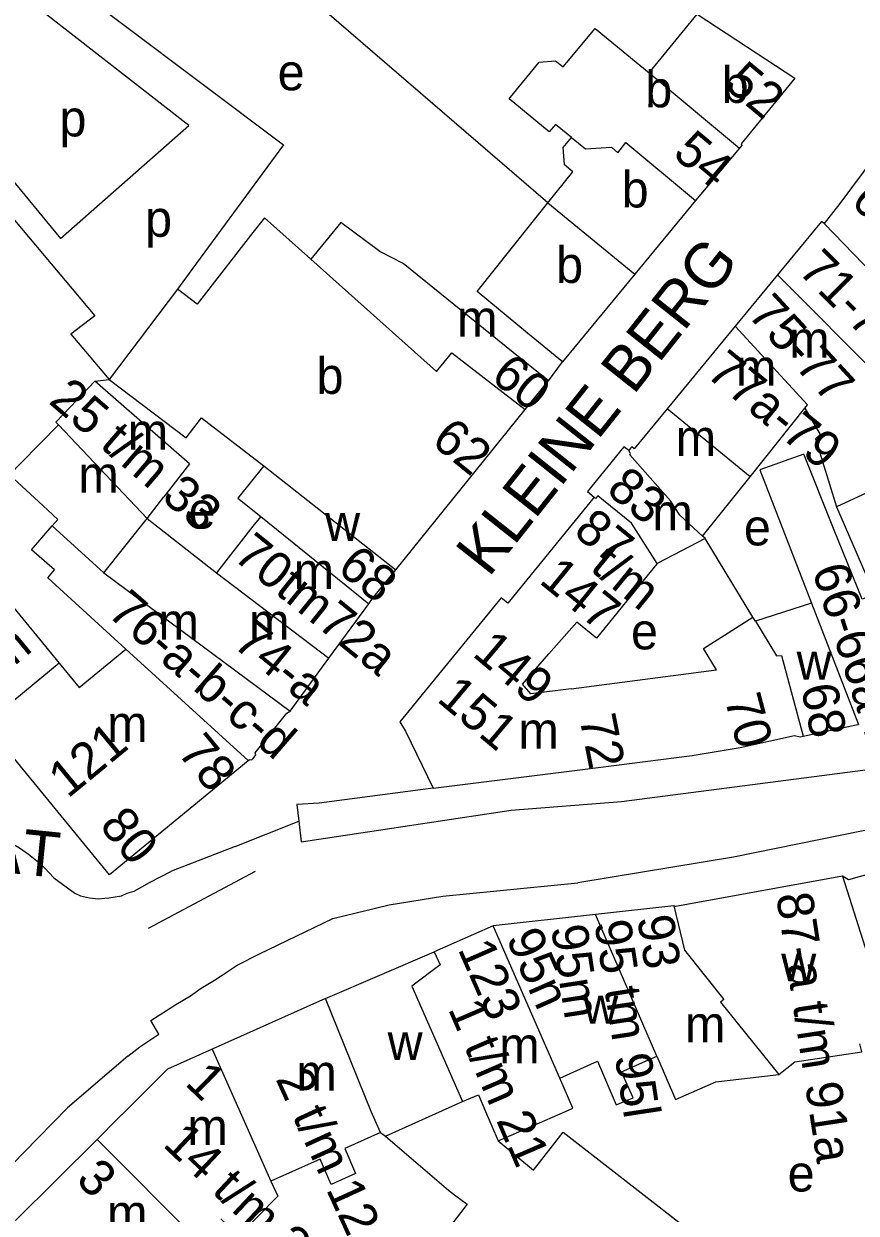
# Model space of a CAD drawing. Extents: x 160673 to 161924, y 382258 to 384145.
# Drawn here: x 160974.8 to 161066.4, y 382888.8 to 383019.8 of the extents above; entities that cross this region are included whole.
import ezdxf

# ---------------------------------------------------------------- set-up
doc = ezdxf.new("R2010")
doc.units = 0
for name, color, linetype in [('BLT_Basislijn', 7, 'Continuous'), ('BLT_Bebouwing', 7, 'Continuous'), ('BLT_Centroide', 7, 'Continuous'), ('BLT_Huisnummer', 7, 'Continuous'), ('BLT_Huisnummer_ tussenligend', 7, 'Continuous'), ('BLT_Huisnummer_reeks', 7, 'Continuous'), ('BLT_Onderdoorgang_en_onderverdeling', 7, 'Continuous'), ('BLT_Onderverdeling_panden', 7, 'Continuous'), ('BLT_Straatnaam', 7, 'Continuous')]:
    doc.layers.add(name, color=color, linetype=linetype)

msp = doc.modelspace()

# ---------------------------------------------------------------- linework, layer by layer
at = {"layer": 'BLT_Basislijn'}
for p, q in [((161032.47, 383000.08), (161006.81, 383022.18)), ((160993.29, 382992.74), (160991.68, 382990.55)), ((161032.54, 382980.45), (161034.1, 382982.55)), ((160982.58, 382980.41), (160984.16, 382980.62)), ((161055.06, 382954.43), (161049.79, 382963.11)), ((161004.83, 382933.8), (161005.04, 382931.98)), ((160998.06, 382929.16), (161005.04, 382931.98)), ((161005.04, 382931.98), (161005.31, 382929.69)), ((161070.35, 382931.54), (161052.91, 382928.01)), ((160998.06, 382929.16), (160991.03, 382926.45)), ((161052.91, 382928.01), (161035.79, 382925.18)), ((161000.23, 382926.42), (160988.47, 382920.16)), ((160978.08, 382925.73), (160980.4, 382924.03)), ((160986.23, 382906.1), (160987.54, 382907.11))]:
    msp.add_line(p, q, dxfattribs=at)
for points in [[(160973.74, 383029.17), (160976.69, 383026.54), (161003.35, 383006.47), (160993.29, 382992.74)], [(160951.81, 383024.3), (160982.58, 382987.62), (160979.94, 382985.6), (160984.16, 382980.62)], [(160963.06, 383015.22), (160978.82, 382996.13), (160992.96, 383008.58), (160973.33, 383023.89)], [(161005.31, 382929.69), (161028.45, 382933.19), (161040.57, 382934.15), (161068.29, 382937.74), (161084.05, 382942.53), (161102.21, 382948.46), (161126.1, 382957.64), (161137.52, 382962.54)], [(161019.84, 382935.61), (161007.3, 382933.96), (161004.83, 382933.8)], [(160969.96, 382931.06), (160971.09, 382930.66), (160972.19, 382930.19), (160973.25, 382929.64), (160974.28, 382929.02), (160975.27, 382928.34), (160976.2, 382927.59), (160977.09, 382926.78), (160978.08, 382925.73)], [(160980.4, 382924.03), (160981.03, 382923.75), (160981.33, 382923.66), (160982, 382923.53), (160983.01, 382923.43), (160983.69, 382923.47), (160984.15, 382923.52), (160985.52, 382923.76), (160986.15, 382924.02), (160986.93, 382924.26), (160988.62, 382925.21), (160991.03, 382926.45)], [(161008.81, 382921.24), (161015.02, 382922.76), (161020.91, 382923.7), (161035.79, 382925.18)], [(160987.54, 382907.11), (160989.65, 382908.51), (160988.76, 382910), (160991.51, 382911.77), (160993.13, 382912.73), (160994.29, 382913.59), (160995.76, 382914.45), (160996.62, 382915), (160998.28, 382916.11), (161000.73, 382917.36), (161008.81, 382921.24)], [(160986.23, 382906.1), (160979.59, 382900.39), (160974.77, 382895.48), (160965.77, 382886.24), (160962.43, 382882.73), (160958.51, 382877.83), (160957.53, 382876.57)], [(161027.01, 382896.76), (161030.91, 382893.53), (161034.17, 382897.73), (161056.14, 382880.6)], [(161014.61, 382897.26), (161021.53, 382891.31), (161022.19, 382890.81), (161023.58, 382889.8), (161012.25, 382875.03), (161002.61, 382861.65), (160999.48, 382858.26), (160999.64, 382857.69), (161009, 382847.54)]]:
    msp.add_lwpolyline(points, dxfattribs=at)
at = {"layer": 'BLT_Bebouwing'}
for p, q in [((161048.73, 383000.34), (161042.04, 382992.21)), ((161042.04, 382992.21), (161034.1, 382982.55)), ((161057.77, 382992.13), (161053.12, 382986.49)), ((160991.68, 382990.55), (160984.16, 382980.62)), ((161053.12, 382986.49), (161045.6, 382977.39)), ((160982.58, 382980.41), (160979.91, 382977.61)), ((160993.03, 382971.31), (160982.58, 382980.41)), ((161029.99, 382977.3), (161032.54, 382980.45)), ((161015.74, 382959.66), (161029.99, 382977.3)), ((161041.58, 382973.03), (161041.38, 382972.78)), ((160993.03, 382971.31), (160990.2, 382967.7)), ((161049.52, 382963.36), (161054.75, 382969.9)), ((161037.57, 382967.65), (161028.06, 382955.98)), ((161064.27, 382966.59), (161068.45, 382956.92)), ((160988.34, 382965.31), (160995.99, 382959.32)), ((161049.79, 382963.11), (161044.52, 382960.34)), ((161049.79, 382963.12), (161049.52, 382963.36)), ((161028.06, 382955.98), (161027.33, 382956.58)), ((161008.35, 382949.91), (161012.75, 382955.91)), ((161061.49, 382955.96), (161055.34, 382953.99)), ((161055.34, 382953.99), (161055.06, 382954.43)), ((161004.09, 382944.1), (161008.35, 382949.91)), ((161008, 382912.42), (161019.95, 382917.58)), ((161014.61, 382897.26), (161023.07, 382901.08)), ((160985.21, 382899.29), (160982.84, 382896.92)), ((161014.05, 382897.68), (161014.61, 382897.26)), ((160982.84, 382896.92), (160973.86, 382887.97))]:
    msp.add_line(p, q, dxfattribs=at)
for points in [[(161043.62, 383014.39), (161048.92, 383020.84)], [(161048.92, 383020.84), (161059.68, 383013.78), (161053.76, 383006.58), (161053.83, 383006.39), (161053.58, 383006.1)], [(161035.07, 383007.26), (161033.31, 383008.71), (161032.63, 383007.89), (161028.21, 383011.52), (161028.35, 383011.69), (161031.52, 383015.55), (161033.33, 383015.72), (161034.18, 383015.03), (161037.67, 383019.28), (161043.62, 383014.39)], [(161032.47, 383000.08), (161035.22, 383003.47), (161034.3, 383004.24), (161034.17, 383006.16), (161035.07, 383007.26)], [(161053.58, 383006.1), (161048.73, 383000.34)], [(161068.48, 383005.17), (161064.61, 383000), (161062.91, 382997.79)], [(161034.1, 382982.55), (161030.24, 382985.73), (161024.69, 382990.29), (161032.47, 383000.08)], [(161001.29, 382998.4), (161000, 382996.8)], [(161006.38, 382993.85), (161001.29, 382998.4)], [(161032.54, 382980.45), (161028.65, 382983.59), (161016.54, 382993.37), (161013.99, 382994.72), (161009.68, 382997.92), (161006.38, 382993.85)], [(161062.91, 382997.79), (161062.61, 382998.01), (161057.77, 382992.13)], [(161000, 382996.8), (160993.87, 382988.89), (160991.68, 382990.55)], [(160984.16, 382980.62), (160992.66, 382974.18), (160994.34, 382976.39), (161001.2, 382971.09)], [(160979.91, 382977.61), (160978.3, 382975.92), (160978.59, 382975.63), (160978.58, 382975.62)], [(161045.6, 382977.39), (161041.99, 382972.97), (161041.72, 382973.19), (161041.58, 382973.03)], [(161054.75, 382969.9), (161060.77, 382977.45)], [(161060.77, 382977.45), (161062.47, 382974.56), (161061.96, 382974.06), (161064.27, 382966.59)], [(160978.58, 382975.62), (160974.46, 382971.4)], [(161041.38, 382972.78), (161040.86, 382973.21), (161036.83, 382968.26), (161037.57, 382967.65)], [(161068.45, 382956.92), (161067.1, 382956.4), (161063.93, 382964.21), (161060.65, 382972.39), (161055.8, 382970.67), (161061.49, 382955.96)], [(160974.46, 382971.4), (160973.2, 382970.11), (160976.88, 382966.73), (160978.52, 382965.21), (160977.89, 382964.49)], [(161001.2, 382971.09), (160998.34, 382967.55), (161000.86, 382965.52)], [(160988.34, 382965.31), (160990.2, 382967.7)], [(160964.45, 382966.67), (160978.68, 382949.37)], [(160986.01, 382950.92), (160977.41, 382958.77), (160978.16, 382959.63), (160975.6, 382961.85), (160977.89, 382964.49)], [(161000.86, 382965.52), (161000, 382964.44), (160995.99, 382959.32)], [(161012.75, 382955.91), (161013.18, 382956.49), (161015.74, 382959.66)], [(161044.52, 382960.34), (161037.82, 382952.13), (161035.65, 382953.9)], [(161027.33, 382956.58), (161016.18, 382942.9), (161016.79, 382941.87), (161019.84, 382935.61)], [(161035.05, 382946.56), (161051.05, 382948.63), (161049.61, 382951), (161055.06, 382954.43)], [(161032.6, 382950.41), (161035.65, 382953.9)], [(160978.68, 382949.37), (160980.88, 382946.7), (160986.01, 382950.92)], [(161035.05, 382946.56), (161030.59, 382945.99), (161029.69, 382947.06), (161032.6, 382950.41)], [(160999.49, 382938.64), (160999.65, 382938.77), (160999.88, 382938.74), (161000.01, 382938.87), (161000.32, 382939.26), (161000.23, 382939.51), (161003.75, 382943.87), (161004.09, 382944.1)], [(160999.49, 382938.63), (160984.22, 382926.07), (160970.55, 382942.67)], [(161060.58, 382941.33), (161066.42, 382942.56), (161066.68, 382942.63)], [(161019.84, 382935.61), (161036.28, 382937.65), (161048.36, 382939.19), (161053.64, 382940.09), (161059.64, 382941.39), (161060.26, 382941.26), (161060.58, 382941.33)], [(161076.29, 382928.52), (161065.6, 382925.49), (161064.91, 382925.91)], [(161064.91, 382925.91), (161046.57, 382922.57), (161046.35, 382922.64)], [(161046.35, 382922.64), (161037.73, 382921.68)], [(161037.73, 382921.68), (161026.46, 382920.43)], [(161026.46, 382920.43), (161019.95, 382917.58)], [(161008, 382912.42), (160995.5, 382906.85)], [(160995.5, 382906.85), (160990.6, 382904.67), (160985.92, 382900), (160985.21, 382899.29)], [(161057.9, 382904.07), (161059.68, 382905.47), (161067.05, 382906.58), (161066.83, 382907.45)], [(161033.8, 382903.66), (161037.93, 382905.53), (161040.01, 382900.71), (161041.86, 382901.51), (161040.6, 382904.37), (161044.47, 382906.1)], [(161044.47, 382906.1), (161046.54, 382901.32), (161050.97, 382903.26), (161057.9, 382904.07)], [(161027.01, 382896.76), (161034.41, 382900), (161035.22, 382900.37), (161033.8, 382903.66)], [(161023.07, 382901.08), (161024.83, 382901.81), (161025.61, 382900), (161027.01, 382896.76)], [(161014.05, 382897.68), (161010.13, 382895.91), (161011.31, 382893.15), (161008.61, 382891.96), (161007.42, 382894.74), (161001.97, 382892.33)], [(161001.97, 382892.33), (161002.74, 382890.65), (160998.39, 382886.24), (160996.48, 382888.16)]]:
    msp.add_lwpolyline(points, dxfattribs=at)
at = {"layer": 'BLT_Onderdoorgang_en_onderverdeling'}
for points in [[(161049.52, 382963.36), (161047.01, 382965.67), (161045.98, 382967.24), (161041.49, 382972.31), (161041.58, 382972.45), (161041.38, 382972.78)], [(161044.52, 382960.34), (161041.69, 382964.77), (161038.6, 382967.3), (161037.98, 382967.8), (161037.74, 382967.51), (161037.57, 382967.65)]]:
    msp.add_lwpolyline(points, dxfattribs=at)
at = {"layer": 'BLT_Onderverdeling_panden'}
for p, q in [((161043.62, 383014.39), (161053.58, 383006.1)), ((161032.47, 383000.08), (161042.04, 382992.21)), ((161072.79, 382987.52), (161062.91, 382997.79)), ((161070.8, 382979.04), (161057.77, 382992.13)), ((161054.75, 382969.9), (161045.6, 382977.39)), ((161001.2, 382971.09), (161015.74, 382959.66)), ((160977.89, 382964.49), (160983.6, 382959.3)), ((160983.6, 382959.3), (160988.34, 382965.31)), ((161000.86, 382965.52), (161012.75, 382955.91)), ((160983.6, 382959.3), (161004.09, 382944.1)), ((160995.99, 382959.32), (161008.35, 382949.91)), ((161061.49, 382955.96), (161066.68, 382942.63)), ((160978.68, 382949.37), (160970.55, 382942.67)), ((161064.91, 382925.91), (161070.28, 382908.96)), ((161046.35, 382922.64), (161047.53, 382917.75)), ((161044.47, 382906.1), (161037.73, 382921.68)), ((161033.8, 382903.66), (161026.46, 382920.43)), ((160995.5, 382906.85), (161001.97, 382892.33)), ((160982.84, 382896.92), (160994.04, 382885.7))]:
    msp.add_line(p, q, dxfattribs=at)
for points in [[(161035.07, 383007.26), (161036.61, 383006), (161039.48, 383006.19), (161040.17, 383005.56), (161041.06, 383006.71), (161048.73, 383000.34)], [(161006.38, 382993.85), (161020.23, 382981.48), (161021.89, 382983.54), (161029.99, 382977.3)], [(161060.77, 382977.45), (161061.07, 382977.82), (161053.12, 382986.49)], [(160988.34, 382965.31), (160978.58, 382975.62)], [(161076.95, 382972.69), (161072.77, 382970.51), (161064.27, 382966.59)], [(161055.34, 382953.99), (161057.66, 382950.16), (161058.22, 382950.23), (161060.58, 382941.33)], [(160999.49, 382938.64), (160986.01, 382950.92)], [(161019.95, 382917.58), (161020.6, 382916.16), (161017.48, 382913.79), (161023.07, 382901.08)], [(161047.53, 382917.75), (161051.86, 382912.34), (161051.5, 382912.05), (161057.9, 382904.07)], [(161014.05, 382897.68), (161013.01, 382900), (161008, 382912.42)]]:
    msp.add_lwpolyline(points, dxfattribs=at)

# ---------------------------------------------------------------- texts
at = {"layer": 'BLT_Centroide'}
for s, p in [('e', (161002.72, 383012.46)), ('b', (161043.2, 383010.59)), ('b', (161051.62, 383011.08)), ('p', (160978.69, 383007.38)), ('b', (161040.6, 382999.56)), ('p', (160988.12, 382996.33)), ('b', (161033.38, 382991.25)), ('m', (161022.48, 382985.34)), ('m', (161059.05, 382983.03)), ('b', (161007, 382979.03)), ('m', (161053.19, 382979.94)), ('m', (160986.22, 382972.88)), ('m', (161046.55, 382972.2)), ('m', (160980.77, 382968.16)), ('e', (160992.91, 382964.2)), ('m', (161043.99, 382963.99)), ('w', (161007.94, 382962.84)), ('e', (161054.06, 382962.34)), ('m', (161004.48, 382957.53)), ('m', (160989.6, 382951.97)), ('m', (160999.58, 382951.94)), ('e', (161041.63, 382950.89)), ('w', (161059.87, 382947.55)), ('m', (160983.95, 382940.7)), ('m', (161029.23, 382939.97)), ('w', (161058.17, 382914.31)), ('w', (161036.36, 382909.66)), ('m', (161047.57, 382907.62)), ('w', (161014.83, 382905.65)), ('m', (161027.12, 382905.29)), ('m', (161004.78, 382902.27)), ('m', (160992.78, 382896.3)), ('e', (161058.88, 382891.18)), ('m', (160983.94, 382886.84))]:
    msp.add_text(s, height=4, dxfattribs=at).set_placement(p)
at = {"layer": 'BLT_Huisnummer'}
for s, rotation, p in [('52', 320.0966, (161051.77, 383012.89)), ('60', 321.0671, (161026.04, 382980.66)), ('68', 321.0575, (161009.13, 382959.55)), ('68', 281.7027, (161060.32, 382946.73))]:
    msp.add_text(s, height=4, rotation=rotation, dxfattribs=at).set_placement(p)
at = {"layer": 'BLT_Huisnummer_ tussenligend'}
for s, rotation, p in [('54', 320.1994, (161046.08, 383005.28)), ('62', 321.0563, (161019.5, 382973.58))]:
    msp.add_text(s, height=4, rotation=rotation, dxfattribs=at).set_placement(p)
at = {"layer": 'BLT_Huisnummer_reeks'}
for s, rotation, p in [('67-a-69', 315.1453, (161065.69, 383000.07)), ('71-73-73a', 315.1458, (161059.89, 382992.47)), ('75-77', 312.5748, (161054.34, 382987.72)), ('77a-79', 320.6852, (161049.75, 382981.05)), ('25 t/m 33', 319.4547, (160977.38, 382978.08)), ('83', 320.8211, (161038.77, 382968.2)), ('87', 320.8176, (161035.15, 382963.62)), ('70tm72a', 321.0581, (160997.67, 382960.91)), ('t/m', 320.8191, (161036.99, 382959.68)), ('147', 320.8176, (161031.38, 382958.29)), ('66-66a-b', 287.822, (161061.54, 382959.64)), ('76-a-b-c-d', 319.0875, (160983.83, 382954.71)), ('74-a', 321.0546, (160997.65, 382951.28)), ('t/m', 39.4577, (160970.15, 382946.09)), ('149', 319.9889, (161024.04, 382950.25)), ('151', 319.9889, (161020.13, 382945.26)), ('70', 284.8449, (161051.92, 382945.45)), ('72', 281.2821, (161035.93, 382943.36)), ('121', 39.4577, (160979.61, 382934.4)), ('78', 309.4576, (160991.58, 382939.51)), ('80', 309.4576, (160982.99, 382931.44)), ('87-a t/m 91a', 278.6857, (161057.6, 382923.84)), ('93', 278.6857, (161042.3, 382921.36)), ('95n', 293.7433, (161027.83, 382919.1)), ('95m', 278.6857, (161032.81, 382920.3)), ('95 tm 95l', 278.6857, (161037.59, 382920.82)), ('123', 293.7433, (161022.52, 382917.89)), ('1 t/m 21', 293.3921, (161021.44, 382911.31)), ('1', 315.3426, (160992.4, 382903.02)), ('2 t/m 12', 294.5909, (161002.45, 382903.6)), ('14 t/m 24', 316.6619, (160989.95, 382896.25)), ('3', 315.0893, (160980.38, 382892.34))]:
    msp.add_text(s, height=4, rotation=rotation, dxfattribs=at).set_placement(p)
at = {"layer": 'BLT_Straatnaam'}
for s, rotation, p in [('KLEINE BERG', 51.5777, (161025.96, 382958.72)), ('WILLEM DE ZWIJGERSTRAAT', 354.1522, (160883.87, 382935.4))]:
    msp.add_text(s, height=4.9999, rotation=rotation, dxfattribs=at).set_placement(p)

doc.saveas('drawing.dxf')
